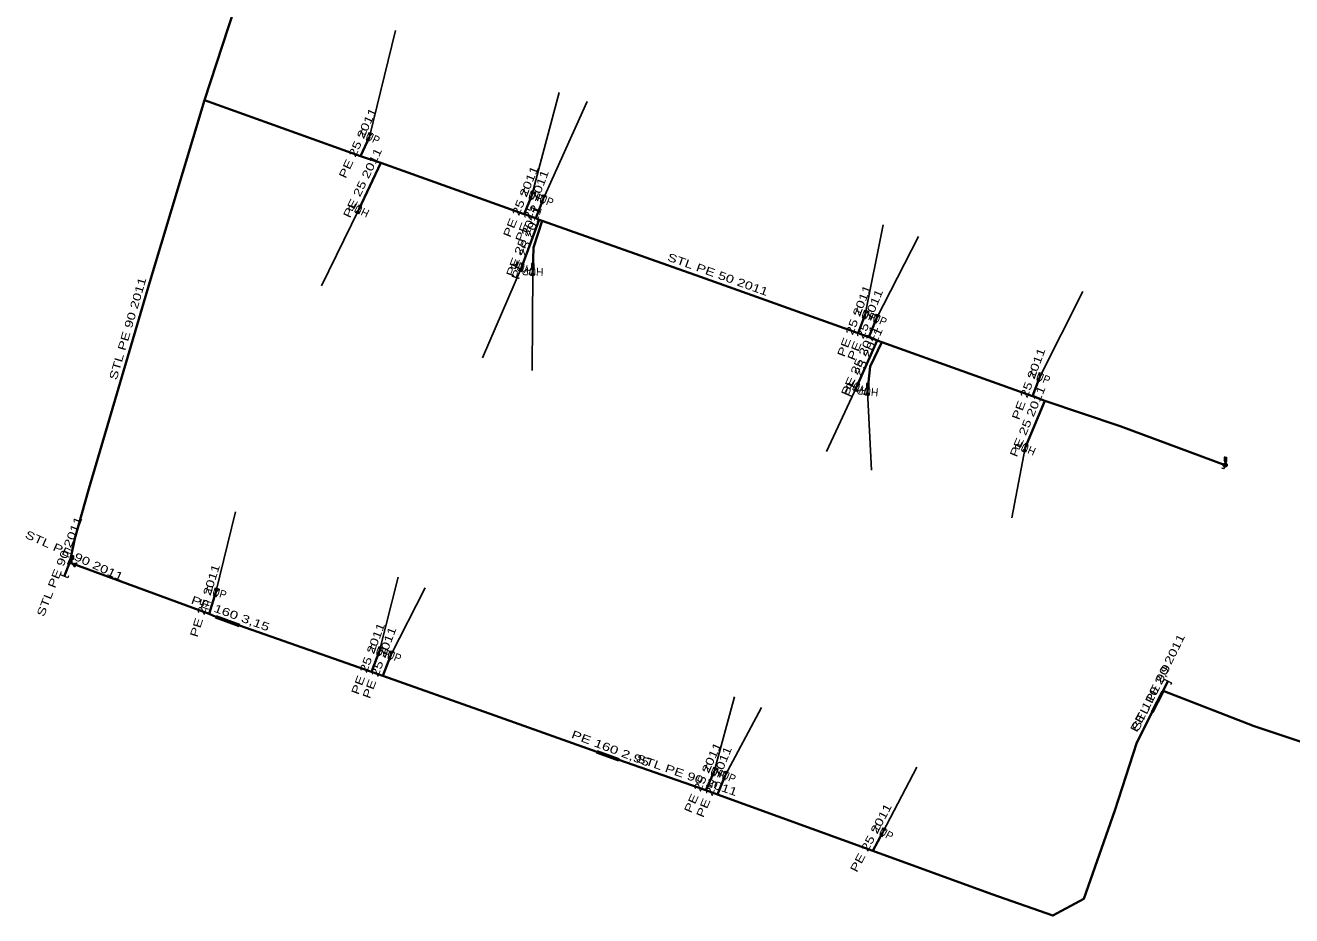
# Model space of a CAD drawing. Extents: x -737484 to -734496, y -1033882 to -1030666.
# Drawn here: x -737484.2 to -737326, y -1031066.7 to -1030955.5 of the extents above; entities that cross this region are included whole.
import ezdxf
from ezdxf.enums import TextEntityAlignment as Align

# ---------------------------------------------------------------- set-up
doc = ezdxf.new("R2010")
doc.units = 0
doc.header["$LTSCALE"] = 0.4
for name, color, linetype, lineweight in [('1', 7, 'Continuous', 13), ('18', 7, 'Continuous', 60), ('22', 7, 'Continuous', 25), ('5', 7, 'Continuous', 35), ('7', 7, 'Continuous', 35)]:
    doc.layers.add(name, color=color, linetype=linetype, lineweight=lineweight)
doc.layers.add('2', color=7, linetype='Continuous')

msp = doc.modelspace()

# ---------------------------------------------------------------- linework, layer by layer
at = {"layer": '1'}
for p, q in [((-737420.765, -1030985.665), (-737420.765, -1030985.315)), ((-737420.84, -1030986.24), (-737420.84, -1030985.74)), ((-737378.99, -1031001.2), (-737378.99, -1031000.7)), ((-737378.915, -1031000.625), (-737378.915, -1031000.275)), ((-737334.481, -1031010.869), (-737334.31, -1031010.4)), ((-737334.31, -1031010.4), (-737334.31, -1031009.9)), ((-737334.235, -1031009.825), (-737334.235, -1031009.475)), ((-737478.305, -1031022.115), (-737478.305, -1031021.765)), ((-737478.38, -1031022.69), (-737478.38, -1031022.19))]:
    msp.add_line(p, q, dxfattribs=at)
for points in [[(-737441.219, -1030968.861), (-737440.853, -1030969.024), (-737441.626, -1030969.775), (-737441.26, -1030969.938)], [(-737420.928, -1030976.161), (-737420.557, -1030976.311), (-737421.302, -1030977.088), (-737420.931, -1030977.238)], [(-737419.547, -1030976.661), (-737419.174, -1030976.804), (-737419.905, -1030977.595), (-737419.532, -1030977.738)], [(-737442.61, -1030979.047), (-737442.972, -1030978.878), (-737442.187, -1030978.141), (-737442.549, -1030977.972)], [(-737422.242, -1030986.258), (-737422.615, -1030986.115), (-737421.884, -1030985.324), (-737422.257, -1030985.181)], [(-737420.84, -1030985.24), (-737420.99, -1030985.24), (-737420.99, -1030985.74), (-737420.84, -1030985.74)], [(-737420.84, -1030985.24), (-737420.69, -1030985.24), (-737420.69, -1030985.74), (-737420.84, -1030985.74)], [(-737420.803, -1030985.278), (-737420.728, -1030985.278), (-737420.728, -1030985.703), (-737420.803, -1030985.703)], [(-737420.657, -1030986.746), (-737421.057, -1030986.732), (-737420.622, -1030985.747), (-737421.022, -1030985.733)], [(-737379.307, -1030991.061), (-737378.934, -1030991.204), (-737379.665, -1030991.995), (-737379.292, -1030992.138)], [(-737377.898, -1030991.561), (-737377.527, -1030991.711), (-737378.272, -1030992.488), (-737377.901, -1030992.638)], [(-737357.497, -1030998.861), (-737357.124, -1030999.004), (-737357.855, -1030999.795), (-737357.482, -1030999.938)], [(-737380.39, -1031001.228), (-737380.756, -1031001.065), (-737379.983, -1031000.314), (-737380.349, -1031000.151)], [(-737378.843, -1031001.718), (-737379.241, -1031001.676), (-737378.738, -1031000.723), (-737379.136, -1031000.681)], [(-737378.99, -1031000.2), (-737379.14, -1031000.2), (-737379.14, -1031000.7), (-737378.99, -1031000.7)], [(-737378.99, -1031000.2), (-737378.84, -1031000.2), (-737378.84, -1031000.7), (-737378.99, -1031000.7)], [(-737378.953, -1031000.238), (-737378.878, -1031000.238), (-737378.878, -1031000.663), (-737378.953, -1031000.663)], [(-737359.311, -1031008.808), (-737359.679, -1031008.652), (-737358.92, -1031007.887), (-737359.288, -1031007.731)], [(-737334.384, -1031010.639), (-737334.406, -1031010.63), (-737334.429, -1031010.619), (-737334.45, -1031010.607), (-737334.469, -1031010.592), (-737334.487, -1031010.575), (-737334.503, -1031010.558), (-737334.518, -1031010.537), (-737334.531, -1031010.516), (-737334.541, -1031010.494), (-737334.549, -1031010.471), (-737334.555, -1031010.448), (-737334.558, -1031010.423), (-737334.559, -1031010.398), (-737334.559, -1031010.374), (-737334.554, -1031010.35), (-737334.549, -1031010.325), (-737334.54, -1031010.302), (-737334.529, -1031010.28), (-737334.517, -1031010.259), (-737334.501, -1031010.239), (-737334.485, -1031010.222), (-737334.466, -1031010.205), (-737334.447, -1031010.191), (-737334.426, -1031010.178), (-737334.404, -1031010.167), (-737334.381, -1031010.16), (-737334.356, -1031010.154), (-737334.333, -1031010.151), (-737334.308, -1031010.149), (-737334.284, -1031010.15), (-737334.259, -1031010.154), (-737334.235, -1031010.16), (-737334.213, -1031010.169), (-737334.19, -1031010.179), (-737334.169, -1031010.192), (-737334.15, -1031010.206), (-737334.132, -1031010.224), (-737334.115, -1031010.242), (-737334.101, -1031010.262), (-737334.088, -1031010.282), (-737334.077, -1031010.305), (-737334.07, -1031010.328), (-737334.063, -1031010.352), (-737334.061, -1031010.376), (-737334.059, -1031010.4), (-737334.06, -1031010.425), (-737334.064, -1031010.45), (-737334.07, -1031010.473), (-737334.079, -1031010.496), (-737334.089, -1031010.519), (-737334.102, -1031010.54), (-737334.116, -1031010.559), (-737334.134, -1031010.577), (-737334.152, -1031010.594), (-737334.172, -1031010.608), (-737334.192, -1031010.621), (-737334.215, -1031010.631), (-737334.238, -1031010.639), (-737334.262, -1031010.646), (-737334.286, -1031010.648), (-737334.311, -1031010.649), (-737334.335, -1031010.649), (-737334.359, -1031010.644)], [(-737334.142, -1031010.451), (-737334.148, -1031010.467), (-737334.155, -1031010.483), (-737334.164, -1031010.497), (-737334.175, -1031010.511), (-737334.186, -1031010.524), (-737334.199, -1031010.535), (-737334.213, -1031010.545), (-737334.227, -1031010.554), (-737334.243, -1031010.562), (-737334.259, -1031010.568), (-737334.276, -1031010.571), (-737334.293, -1031010.574), (-737334.31, -1031010.575), (-737334.327, -1031010.574), (-737334.344, -1031010.571), (-737334.361, -1031010.567), (-737334.377, -1031010.561), (-737334.393, -1031010.553), (-737334.407, -1031010.545), (-737334.421, -1031010.534), (-737334.434, -1031010.522), (-737334.445, -1031010.51), (-737334.455, -1031010.496), (-737334.464, -1031010.482), (-737334.472, -1031010.465), (-737334.478, -1031010.449), (-737334.481, -1031010.433), (-737334.484, -1031010.416), (-737334.485, -1031010.399), (-737334.484, -1031010.381), (-737334.481, -1031010.364), (-737334.477, -1031010.347), (-737334.471, -1031010.331), (-737334.463, -1031010.316), (-737334.455, -1031010.301), (-737334.444, -1031010.288), (-737334.432, -1031010.275), (-737334.42, -1031010.264), (-737334.406, -1031010.253), (-737334.391, -1031010.244), (-737334.375, -1031010.237), (-737334.359, -1031010.231), (-737334.342, -1031010.227), (-737334.326, -1031010.224), (-737334.309, -1031010.224), (-737334.291, -1031010.225), (-737334.275, -1031010.228), (-737334.257, -1031010.232), (-737334.241, -1031010.238), (-737334.226, -1031010.246), (-737334.211, -1031010.254), (-737334.198, -1031010.265), (-737334.185, -1031010.276), (-737334.173, -1031010.288), (-737334.163, -1031010.303), (-737334.154, -1031010.318), (-737334.147, -1031010.333), (-737334.141, -1031010.349), (-737334.138, -1031010.366), (-737334.134, -1031010.383), (-737334.134, -1031010.4), (-737334.135, -1031010.417), (-737334.137, -1031010.435)], [(-737334.31, -1031009.4), (-737334.46, -1031009.4), (-737334.46, -1031009.9), (-737334.31, -1031009.9)], [(-737334.453, -1031010.355), (-737334.448, -1031010.341), (-737334.441, -1031010.328), (-737334.434, -1031010.315), (-737334.425, -1031010.303), (-737334.415, -1031010.293), (-737334.404, -1031010.283), (-737334.391, -1031010.274), (-737334.379, -1031010.267), (-737334.366, -1031010.261), (-737334.352, -1031010.255), (-737334.338, -1031010.252), (-737334.323, -1031010.25), (-737334.308, -1031010.249), (-737334.293, -1031010.25), (-737334.279, -1031010.252), (-737334.265, -1031010.256), (-737334.251, -1031010.261), (-737334.238, -1031010.267), (-737334.225, -1031010.275), (-737334.213, -1031010.284), (-737334.203, -1031010.294), (-737334.193, -1031010.305), (-737334.184, -1031010.317), (-737334.177, -1031010.33), (-737334.17, -1031010.343), (-737334.165, -1031010.356), (-737334.162, -1031010.371), (-737334.16, -1031010.386), (-737334.159, -1031010.4), (-737334.16, -1031010.415), (-737334.162, -1031010.43), (-737334.166, -1031010.443), (-737334.171, -1031010.457), (-737334.177, -1031010.471), (-737334.185, -1031010.483), (-737334.193, -1031010.495), (-737334.204, -1031010.506), (-737334.215, -1031010.516), (-737334.226, -1031010.525), (-737334.239, -1031010.533), (-737334.253, -1031010.538), (-737334.266, -1031010.543), (-737334.281, -1031010.547), (-737334.296, -1031010.549), (-737334.31, -1031010.549), (-737334.324, -1031010.548), (-737334.339, -1031010.546), (-737334.353, -1031010.543), (-737334.367, -1031010.538), (-737334.381, -1031010.531), (-737334.393, -1031010.523), (-737334.405, -1031010.515), (-737334.416, -1031010.505), (-737334.426, -1031010.494), (-737334.434, -1031010.482), (-737334.442, -1031010.469), (-737334.448, -1031010.456), (-737334.453, -1031010.442), (-737334.457, -1031010.428), (-737334.459, -1031010.413), (-737334.459, -1031010.398), (-737334.459, -1031010.383), (-737334.456, -1031010.37)], [(-737334.381, -1031010.377), (-737334.379, -1031010.37), (-737334.375, -1031010.364), (-737334.372, -1031010.358), (-737334.367, -1031010.352), (-737334.362, -1031010.346), (-737334.356, -1031010.341), (-737334.35, -1031010.337), (-737334.344, -1031010.333), (-737334.337, -1031010.33), (-737334.331, -1031010.327), (-737334.323, -1031010.325), (-737334.316, -1031010.325), (-737334.309, -1031010.324), (-737334.301, -1031010.325), (-737334.294, -1031010.325), (-737334.288, -1031010.328), (-737334.28, -1031010.33), (-737334.274, -1031010.333), (-737334.268, -1031010.337), (-737334.261, -1031010.342), (-737334.256, -1031010.347), (-737334.251, -1031010.352), (-737334.246, -1031010.358), (-737334.242, -1031010.364), (-737334.239, -1031010.371), (-737334.238, -1031010.378), (-737334.235, -1031010.385), (-737334.235, -1031010.393), (-737334.234, -1031010.4), (-737334.235, -1031010.408), (-737334.236, -1031010.414), (-737334.238, -1031010.421), (-737334.24, -1031010.428), (-737334.244, -1031010.435), (-737334.247, -1031010.441), (-737334.251, -1031010.447), (-737334.257, -1031010.453), (-737334.261, -1031010.457), (-737334.269, -1031010.462), (-737334.274, -1031010.466), (-737334.28, -1031010.469), (-737334.288, -1031010.471), (-737334.295, -1031010.473), (-737334.303, -1031010.474), (-737334.309, -1031010.475), (-737334.318, -1031010.474), (-737334.324, -1031010.473), (-737334.331, -1031010.471), (-737334.339, -1031010.469), (-737334.345, -1031010.465), (-737334.351, -1031010.462), (-737334.357, -1031010.458), (-737334.363, -1031010.452), (-737334.367, -1031010.447), (-737334.372, -1031010.44), (-737334.375, -1031010.434), (-737334.378, -1031010.428), (-737334.381, -1031010.421), (-737334.383, -1031010.413), (-737334.384, -1031010.406), (-737334.384, -1031010.399), (-737334.384, -1031010.391), (-737334.383, -1031010.385)], [(-737334.31, -1031009.4), (-737334.16, -1031009.4), (-737334.16, -1031009.9), (-737334.31, -1031009.9)], [(-737334.273, -1031009.438), (-737334.198, -1031009.438), (-737334.198, -1031009.863), (-737334.273, -1031009.863)], [(-737478.38, -1031021.69), (-737478.53, -1031021.69), (-737478.53, -1031022.19), (-737478.38, -1031022.19)], [(-737478.38, -1031021.69), (-737478.23, -1031021.69), (-737478.23, -1031022.19), (-737478.38, -1031022.19)], [(-737478.343, -1031021.728), (-737478.268, -1031021.728), (-737478.268, -1031022.153), (-737478.343, -1031022.153)], [(-737477.801, -1031022.619), (-737478.045, -1031023.167), (-737478.714, -1031022.212), (-737478.958, -1031022.76)], [(-737460.455, -1031025.733), (-737460.072, -1031025.85), (-737460.747, -1031026.689), (-737460.364, -1031026.806)], [(-737439.987, -1031033.081), (-737439.614, -1031033.224), (-737440.345, -1031034.015), (-737439.972, -1031034.158)], [(-737438.567, -1031033.591), (-737438.194, -1031033.734), (-737438.925, -1031034.525), (-737438.552, -1031034.668)], [(-737398.139, -1031048.121), (-737397.773, -1031048.284), (-737398.546, -1031049.035), (-737398.18, -1031049.198)], [(-737396.768, -1031048.621), (-737396.397, -1031048.771), (-737397.142, -1031049.548), (-737396.771, -1031049.698)], [(-737377.011, -1031055.694), (-737376.658, -1031055.882), (-737377.481, -1031056.577), (-737377.128, -1031056.765)]]:
    msp.add_lwpolyline(points, close=True, dxfattribs=at)
for points in [[(-737334.373, -1031009.844), (-737334.138, -1031009.93), (-737334.481, -1031010.869), (-737334.715, -1031010.784)], [(-737478.823, -1031024.255), (-737478.913, -1031024.489), (-737479.846, -1031024.13), (-737479.757, -1031023.897)], [(-737342.038, -1031037.375), (-737341.929, -1031037.15), (-737341.03, -1031037.589), (-737341.14, -1031037.813)]]:
    msp.add_lwpolyline(points, dxfattribs=at)
at = {"layer": '18'}
for p, q in [((-737460.43, -1031029.34), (-737457.47, -1031030.42)), ((-737343.45, -1031041.26), (-737342.12, -1031038.68)), ((-737412.82, -1031046.2), (-737410.09, -1031047.23))]:
    msp.add_line(p, q, dxfattribs=at)
at = {"layer": '22'}
for p, q in [((-737441.24, -1030969.4), (-737437.976, -1030956.129)), ((-737420.93, -1030976.7), (-737417.537, -1030963.868)), ((-737419.54, -1030977.2), (-737414.031, -1030964.993)), ((-737442.58, -1030978.51), (-737447.236, -1030988.011)), ((-737379.3, -1030991.6), (-737377.055, -1030980.405)), ((-737377.9, -1030992.1), (-737372.623, -1030981.86)), ((-737422.25, -1030985.72), (-737427.128, -1030997.007)), ((-737420.84, -1030986.24), (-737420.91, -1030998.595)), ((-737357.49, -1030999.4), (-737352.118, -1030988.739)), ((-737380.37, -1031000.69), (-737384.133, -1031008.715)), ((-737378.99, -1031001.2), (-737378.51, -1031011.03)), ((-737359.3, -1031008.27), (-737360.982, -1031016.983)), ((-737460.41, -1031026.27), (-737457.952, -1031016.256)), ((-737439.98, -1031033.62), (-737437.645, -1031024.392)), ((-737438.56, -1031034.13), (-737434.272, -1031025.715)), ((-737398.16, -1031048.66), (-737395.642, -1031039.341)), ((-737396.77, -1031049.16), (-737392.269, -1031040.664)), ((-737377.07, -1031056.23), (-737372.822, -1031048.138))]:
    msp.add_line(p, q, dxfattribs=at)
at = {"layer": '5'}
for p, q in [((-737478.69, -1031022.55), (-737479.38, -1031024.31)), ((-737478.38, -1031022.69), (-737478.69, -1031022.55)), ((-737342.08, -1031038.59), (-737341.48, -1031037.37))]:
    msp.add_line(p, q, dxfattribs=at)
for points in [[(-737442.45, -1030903.04), (-737445.99, -1030912.93), (-737448.15, -1030919.23), (-737453.26, -1030936.83), (-737457.33, -1030951.08), (-737461.84, -1030964.85)], [(-737461.84, -1030964.85), (-737468.69, -1030987.54), (-737476.28, -1031013.38), (-737478.04, -1031019.58), (-737478.69, -1031022.55)], [(-737461.84, -1030964.85), (-737442.34, -1030971.82), (-737439.82, -1030972.67), (-737421.89, -1030979.07), (-737420.43, -1030979.57), (-737420.01, -1030979.77), (-737419.65, -1030979.89), (-737399.86, -1030986.89), (-737380.19, -1030993.93), (-737378.86, -1030994.43), (-737377.79, -1030994.84), (-737377.23, -1030995.05), (-737358.4, -1031001.82), (-737356.86, -1031002.39), (-737347.43, -1031005.56), (-737334.31, -1031010.4)], [(-737342.08, -1031038.59), (-737342.12, -1031038.68), (-737343.45, -1031041.26), (-737345.37, -1031045.04), (-737348.12, -1031053.54), (-737351.97, -1031064.56), (-737355.87, -1031066.67), (-737363.49, -1031063.97), (-737378.32, -1031058.59), (-737397.75, -1031051.53), (-737399.2, -1031051), (-737410.09, -1031047.23), (-737412.82, -1031046.2), (-737425.55, -1031041.66), (-737439.55, -1031036.73), (-737440.97, -1031036.24), (-737457.47, -1031030.42), (-737460.43, -1031029.34), (-737461.27, -1031029), (-737478.38, -1031022.69)], [(-737319.71, -1031046.67), (-737330.68, -1031043.02), (-737342.08, -1031038.59)]]:
    msp.add_lwpolyline(points, dxfattribs=at)
at = {"layer": '7'}
for p, q in [((-737442.34, -1030971.82), (-737441.24, -1030969.4)), ((-737439.82, -1030972.67), (-737442.58, -1030978.51)), ((-737421.89, -1030979.07), (-737420.93, -1030976.7)), ((-737420.43, -1030979.57), (-737419.54, -1030977.2)), ((-737420.01, -1030979.77), (-737422.25, -1030985.72)), ((-737380.19, -1030993.93), (-737379.3, -1030991.6)), ((-737378.86, -1030994.43), (-737377.9, -1030992.1)), ((-737377.79, -1030994.84), (-737380.37, -1031000.69)), ((-737358.4, -1031001.82), (-737357.49, -1030999.4)), ((-737356.86, -1031002.39), (-737359.3, -1031008.27)), ((-737461.27, -1031029), (-737460.41, -1031026.27)), ((-737440.97, -1031036.24), (-737439.98, -1031033.62)), ((-737439.55, -1031036.73), (-737438.56, -1031034.13)), ((-737399.2, -1031051), (-737398.16, -1031048.66)), ((-737397.75, -1031051.53), (-737396.77, -1031049.16)), ((-737378.32, -1031058.59), (-737377.07, -1031056.23))]:
    msp.add_line(p, q, dxfattribs=at)
for points in [[(-737419.65, -1030979.89), (-737420.72, -1030983.22), (-737420.84, -1030986.24)], [(-737377.23, -1030995.05), (-737378.68, -1030998.1), (-737378.99, -1031001.2)]]:
    msp.add_lwpolyline(points, dxfattribs=at)

# ---------------------------------------------------------------- texts
at = {"layer": '18', "width": 1.4}
for s, rotation, p in [('PE 160 3,15', 339.955, (-737458.7779, -1031029.4099)), ('PE 110 2,9', 62.729, (-737343.2292, -1031039.7406)), ('PE 160 2,95', 339.329, (-737411.278, -1031046.2471))]:
    msp.add_text(s, height=1, rotation=rotation, dxfattribs=at).set_placement(p, align=Align.CENTER)
at = {"layer": '2', "width": 0.95}
for rotation, p in [(336, (-737441.4429, -1030969.8567)), (338, (-737421.1168, -1030977.163)), (339, (-737419.7187, -1030977.6663)), (155, (-737442.3682, -1030978.0564)), (159, (-737422.0703, -1030985.2527)), (178, (-737420.8221, -1030985.7397)), (339, (-737379.4787, -1030992.0663)), (338, (-737378.0868, -1030992.563)), (339, (-737357.6687, -1030999.8663)), (156, (-737380.1661, -1031000.2323)), (174, (-737378.9372, -1031000.7023)), (157, (-737359.1041, -1031007.8097)), (343, (-737460.5557, -1031026.7478)), (339, (-737440.1587, -1031034.0863)), (339, (-737438.7387, -1031034.5963)), (336, (-737398.3629, -1031049.1167)), (338, (-737396.9568, -1031049.623)), (332, (-737377.3042, -1031056.671))]:
    msp.add_text('HUP', height=1, rotation=rotation, dxfattribs=at).set_placement(p, align=Align.CENTER)
at = {"layer": '5', "width": 1.35}
for s, rotation, p in [('STL PE 50 2011', 340.307, (-737397.8755, -1030987.0689)), ('STL PE 90 2011', 73.631, (-737470.9607, -1030993.4984)), ('STL PE 90 2011', 68.593, (-737479.5004, -1031023.247)), ('STL PE 90 2011', 335.695, (-737478.3288, -1031022.1636)), ('STL PE 90 2011', 63.812, (-737342.2281, -1031037.7587)), ('STL PE 90 2011', 340.905, (-737401.7451, -1031049.589))]:
    msp.add_text(s, height=1, rotation=rotation, dxfattribs=at).set_placement(p, align=Align.CENTER)
at = {"layer": '7', "width": 1.35}
for rotation, p in [(65.556, (-737442.2444, -1030970.4024)), (64.704, (-737441.6519, -1030975.3761)), (67.949, (-737421.8734, -1030977.6967)), (69.417, (-737420.453, -1030978.2088)), (69.37, (-737421.5973, -1030982.5682)), (72.187, (-737421.1233, -1030982.84)), (69.094, (-737380.211, -1030992.5859)), (67.608, (-737378.8412, -1030993.074)), (66.201, (-737379.5369, -1030997.5628)), (64.573, (-737379.0751, -1030997.7667)), (69.392, (-737358.412, -1031000.4335)), (67.463, (-737358.5415, -1031005.1381)), (72.515, (-737461.3158, -1031027.4842)), (69.3, (-737440.942, -1031034.7532)), (69.155, (-737439.5217, -1031035.2514)), (66.038, (-737399.1367, -1031049.6266)), (67.535, (-737397.7218, -1031050.1536)), (62.092, (-737378.1367, -1031057.1755))]:
    msp.add_text('PE 25 2011', height=1, rotation=rotation, dxfattribs=at).set_placement(p, align=Align.CENTER)

doc.saveas('drawing.dxf')
